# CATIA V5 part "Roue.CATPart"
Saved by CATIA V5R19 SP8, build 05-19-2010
Part number: Roue
Bounding box of the stored display mesh (mm): x 0 to 89, y -167.5 to 167.5, z -167.31 to 167.31
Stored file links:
  E:\IAO_2010\iao\IAO_MMS_Groupe2\IAO_MMS_Groupe2\OK\nmoissenet\nmoissenet\nmoissenet\Roue.CATPart
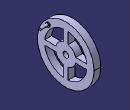
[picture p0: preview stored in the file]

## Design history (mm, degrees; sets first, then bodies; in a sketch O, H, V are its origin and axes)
Body1 (main body)
  Sketch1 on yz-plane, origin (0, 0, 0), H (0, 1, 0), V (0, 0, 1)
    circle A1 centre (0, 0) radius 167.5
    arc A2 centre (0, 0) radius 60 from (-58.2216, -14.5) to (-14.5, -58.2216) ccw
    point P1 (-14.5, 124.1562)
    line L1 (-14.5, 124.1562) -> (-14.5, 58.2216)
    point P2 (-14.5, 58.2216)
    line L2 (14.5, 124.1562) -> (14.5, 58.2216)
    point P4 (14.5, 58.2216)
    line L3 (-124.1562, 14.5) -> (-58.2216, 14.5)
    line L4 (-124.1562, -14.5) -> (-58.2216, -14.5)
    point P9 (-14.5, -124.1562)
    line L5 (-14.5, -124.1562) -> (-14.5, -58.2216)
    point P11 (124.1562, 14.5)
    line L6 (124.1562, 14.5) -> (58.2216, 14.5)
    point P12 (58.2216, 14.5)
    point P13 (124.1562, -14.5)
    line L7 (124.1562, -14.5) -> (58.2216, -14.5)
    point P14 (58.2216, -14.5)
    point P15 (14.5, -58.2216)
    line L8 (14.5, -58.2216) -> (14.5, -124.1562)
    arc A3 centre (0, 0) radius 125 from (14.5, -124.1562) to (124.1562, -14.5) ccw
    arc A4 centre (0, 0) radius 125 from (124.1562, 14.5) to (14.5, 124.1562) ccw
    arc A5 centre (0, 0) radius 125 from (-124.1562, -14.5) to (-14.5, -124.1562) ccw
    arc A6 centre (0, 0) radius 125 from (-14.5, 124.1562) to (-124.1562, 14.5) ccw
    arc A7 centre (0, 0) radius 60 from (14.5, -58.2216) to (58.2216, -14.5) ccw
    arc A8 centre (0, 0) radius 60 from (-14.5, 58.2216) to (-58.2216, 14.5) ccw
    arc A9 centre (0, 0) radius 60 from (58.2216, 14.5) to (14.5, 58.2216) ccw
    radius A1 = 167.5
    radius A2 = 60
    distance L1 L2 = 29
    distance V L1 = 14.5
    distance L7 L6 = 29
    distance L7 H = 14.5
    radius A3 = 125
    coincidence: P2 A2, P4 A2, P9 L1, P11 L3, P12 A2, P13 L4, P14 A2, P15 L2, P15 A2, A3 P1, A3 A4, A4 A5, A4 A6, A2 A7, A7 A8, A7 A9
    vertical: L1 V, L2 V, L5 V, L8 V
    horizontal: L3 H, L4 H, L6 H, L7 H
  Pad1: profile Sketch1, direction (1, 0, 0), length 40
  Sketch2 on end face of Pad1, origin (40, 0, 0), H (0, 1, 0), V (0, 0, 1)
    circle A1 centre (-103.485, 103.3437) radius 12
    point P1 (-103.485, 103.3437)
    reference projected circle E1 centre (0, 0) radius 167.5 from edge [face of Pad1 from Sketch1.A1 | end face of Pad1]
    radius A1 = 12
    distance P1 E1 = 21.25
    distance V P1 = 103.485
  Pad2: profile Sketch2, direction (1, 0, 0), length 5
  Sketch3 on end face of Pad2, origin (45, 0, 0), H (0, 1, 0), V (0, 0, 1)
    circle A1 centre (-103.485, 103.3437) radius 7.5
    point P1 (-103.485, 103.3437)
    reference projected circle E1 centre (0, 0) radius 167.5 from edge [face of Pad1 from Sketch1.A1 | end face of Pad1]
    distance P1 E1 = 21.25
    radius A1 = 7.5
    distance V P1 = 103.485
  Pad3: profile Sketch3, direction (1, 0, 0), length 44
  Sketch4 on end face of Pad1, origin (40, 0, 0), H (0, 1, 0), V (0, 0, 1)
    circle A1 centre (0, 0) radius 16.5
    radius A1 = 16.5
  Pocket1: profile Sketch4, direction (-1, 0, 0), through (limit type 6)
